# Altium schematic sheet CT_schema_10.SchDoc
size 147 x 119 mm
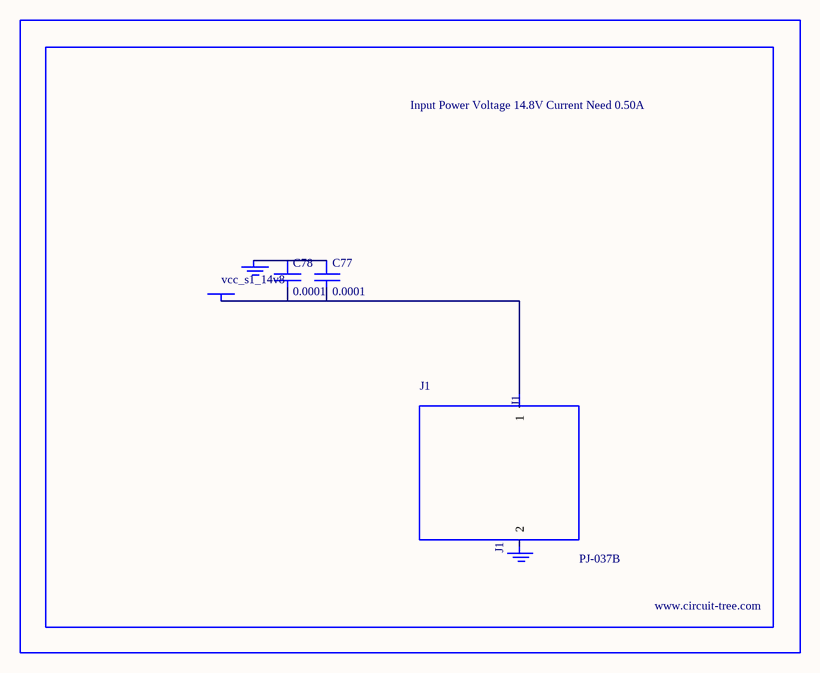
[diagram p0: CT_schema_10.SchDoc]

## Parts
BORDER9  (no value)
C77  0.0001  [EXV-9H]
C78  0.0001  [EXV-9H]
GND_INSTANCE_9_0  (no value)
GND_INSTANCE_9_1  (no value)
J1  PJ-037B  [PJ-037B_PACKAGE]
POWER_INSTANCE_9_0  vcc_s1_14v8

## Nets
NetC77_1: C77.1 C78.1 GND_INSTANCE_9_0.0(GND)
NetC77_2: C77.2 C78.2 J1.1 POWER_INSTANCE_9_0.0(PWR)

Not connected (* = marked no-connect by the designer): GND_INSTANCE_9_1 0(GND); J1 2

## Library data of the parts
BORDER9 = BORDER_PAGE9
C77 C78 = EDK107M035A9HAA
GND_INSTANCE_9_0 GND_INSTANCE_9_1 = GND
POWER_INSTANCE_9_0 = PWR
